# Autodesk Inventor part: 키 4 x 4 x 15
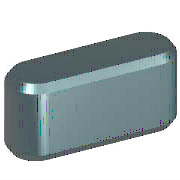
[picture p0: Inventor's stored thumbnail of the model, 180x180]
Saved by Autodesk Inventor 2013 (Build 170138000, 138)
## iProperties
IsCustomPart: 1
Created: 2012-02
Part Number: 키 4 x 4 x 15
Material: 강철, 연강
Description: 키 및 해당 키홈
Document SubType Name: Modeling
Standard: KS B 1311
Designer: test
Standards Organization: KS
Language: ko-KR
Size Designation: 4 x 4 x 10
Categories: <MemberInstance><Categories><Category DisplayName="샤프트 부품" InternalName="7f7aeb1f-a693-4053-b835-cee3144e0d98" Mnemonic="SHFT"><Category DisplayName="키" Interna
Density: 1 g/cm^3
Author: test
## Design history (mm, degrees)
workplane "Work Plane1"
workplane "Work Plane2"
sketch "스케치1"
  geometry: L1 (2, 2)-(13, 2); L2 (13, -2)-(2, -2); L3 (0, 8.8)-(0, -3.8) reference; L4 (-2, 0)-(12, 0) reference; L5 (15, 0)-(15, 7); A1 r 2 centre (2, 0) between (2, 2) and (2, -2); A2 r 2 centre (13, 0) between (13, -2) and (13, 2)
  constraints: 6 end point, 5 point on circle, 4 tangent, 3 point on line, 2 centre point, 1 horizontal, 1 parallel, 1 perpendicular
  dimensions: "d0" = 2 radius of A1 (= 0.5 x PB); "d13" = 2 radius of A2 (= 0.5 x PB); "d14" = 15 distance between parallel lines of L5 L3 (= NLG)
extrude "본체1" new body sketch "스케치1" taper "d3" = 0 deg; stored distance "d4" = 10
workplane "Work Plane3"
body "Solid1"
chamfer "모따기1" distance "d8" = 0.25 (= PHH); stored, may be unused: second distance "d9" = 0.25 (= PHH), angle "d15" = 45 deg
other parameters: "d1" = -2.5 (= -PNT), "d2" = 1.5 (= PH - PNT), "NLG" = 15 [user parameter; used in 3 equation terms], "PB" = 4 [user parameter; used in 2 equation terms], "PNT" = 2.5 [user parameter; used in 2 equation terms], "PH" = 4 [user parameter; used in 1 equation term], "PHH" = 0.25 [user parameter; used in 2 equation terms], "d10" = 0, "d16" = 0, "d17" = 0, "d18" = 0, "PLB2" = 15 (= NLG) [user parameter], "WDMAX" = 12 [user parameter], "PLB1" = 15 (= NLG) [user parameter], "RR" = 0.08 [user parameter], "PUEB" = 1.8 [user parameter]
